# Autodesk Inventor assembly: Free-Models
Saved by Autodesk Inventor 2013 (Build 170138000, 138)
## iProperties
Created: 2021-02
Part Number: Free-Models
Document SubType Name: Assembly
Designer: Fede
Author: Fede
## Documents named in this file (3)
- C:\0000 FEDE\16GB\0000 INTERIOR\DE_TMP_BAS\BAS_DTON - demora conexion al energizar\DTON_MANUAL\img\INVENTOR\BAS_DTON - SIN R\Free-Models.iam
- C:\0000 FEDE\16GB\0000 INTERIOR\DE_TMP_BAS\BAS_DTON - demora conexion al energizar\DTON_MANUAL\img\INVENTOR\BAS_DTON - SIN R\jump.iam
- C:\0000 FEDE\16GB\0000 INTERIOR\DE_TMP_BAS\BAS_DTON - demora conexion al energizar\DTON_MANUAL\img\INVENTOR\BAS_DTON - SIN R\pin4x1.iam
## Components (2 placed, 2 different names)
1. jump:1 [sub-assembly]
2. pin4x1:1 [sub-assembly]
